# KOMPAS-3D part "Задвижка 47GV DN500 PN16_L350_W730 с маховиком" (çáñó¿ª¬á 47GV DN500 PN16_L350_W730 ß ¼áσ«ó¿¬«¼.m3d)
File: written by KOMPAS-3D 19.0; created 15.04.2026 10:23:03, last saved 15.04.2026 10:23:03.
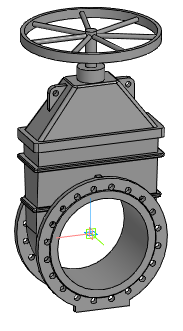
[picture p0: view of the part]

Document properties: Автор: Евгений; Полное имя файла: Z:\3.Личные\kachalov\3d для проектировщиков\2.1 Тип 47GV, 47GV.Z\Задвижка 47GV_DN40-DN600\stp_Задвижка 47GV\Задвижка 47GV DN500 PN16_L350_W730 с маховиком.m3d

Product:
- Part/product: Задвижка 47GV DN500 PN16_L350_W730 с маховиком

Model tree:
1. Операция без истории:1  (labels: Задвижка 47GV DN500 PN16_L350_W730 с маховиком)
